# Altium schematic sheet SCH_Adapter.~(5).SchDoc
size A
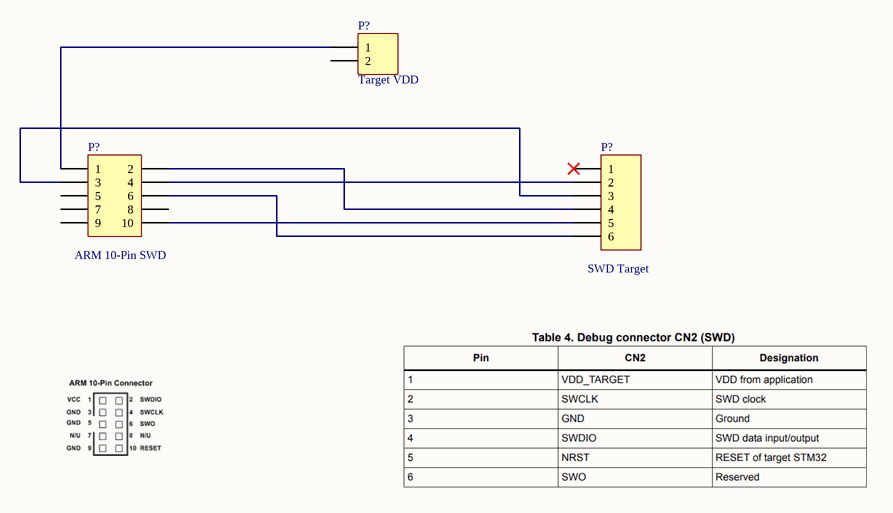
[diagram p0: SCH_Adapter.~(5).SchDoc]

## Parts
(Parts that share a designator on the sheet are numbered #1, #2 ... from top to bottom, then left to right.)
P?#1  Target VDD  [HDR1X2]
P?#2  ARM 10-Pin SWD  [HDR2X5]
P?#3  SWD Target  [HDR1X6]

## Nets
NetP?#1_1: P?#1.1 P?#2.1
NetP?#2_2: P?#2.2 P?#3.4
NetP?#2_3: P?#2.3 P?#3.3
NetP?#2_4: P?#2.4 P?#3.2
NetP?#2_6: P?#2.6 P?#3.6
NetP?#2_10: P?#2.10 P?#3.5

Not connected (* = marked no-connect by the designer): P?#1 2; P?#2 5 7 8 9; P?#3 1*

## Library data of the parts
P?#1 = Header 2: Header, 2-Pin
P?#2 = Header 5X2: Header, 5-Pin, Dual row
P?#3 = Header 6: Header, 6-Pin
